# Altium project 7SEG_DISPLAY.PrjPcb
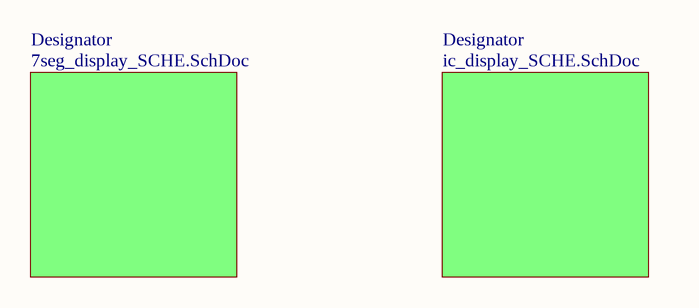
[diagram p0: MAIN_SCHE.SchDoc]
3 sheets, 658 parts. Net scope: global (net labels, ports and power ports of the same name join across sheets).
Board file: 7SEG_PCB.PcbDoc
Sheets:
  MAIN_SCHE.SchDoc
    Designator = 7seg_display_SCHE.SchDoc
    Designator = ic_display_SCHE.SchDoc

## Sheet MAIN_SCHE.SchDoc
size A; SheetNumber: 1; SheetTotal: 3

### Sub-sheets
Designator = 7seg_display_SCHE.SchDoc: no entries
Designator = ic_display_SCHE.SchDoc: no entries

## Sheet 7seg_display_SCHE.SchDoc
size C; SheetNumber: 3; SheetTotal: 3
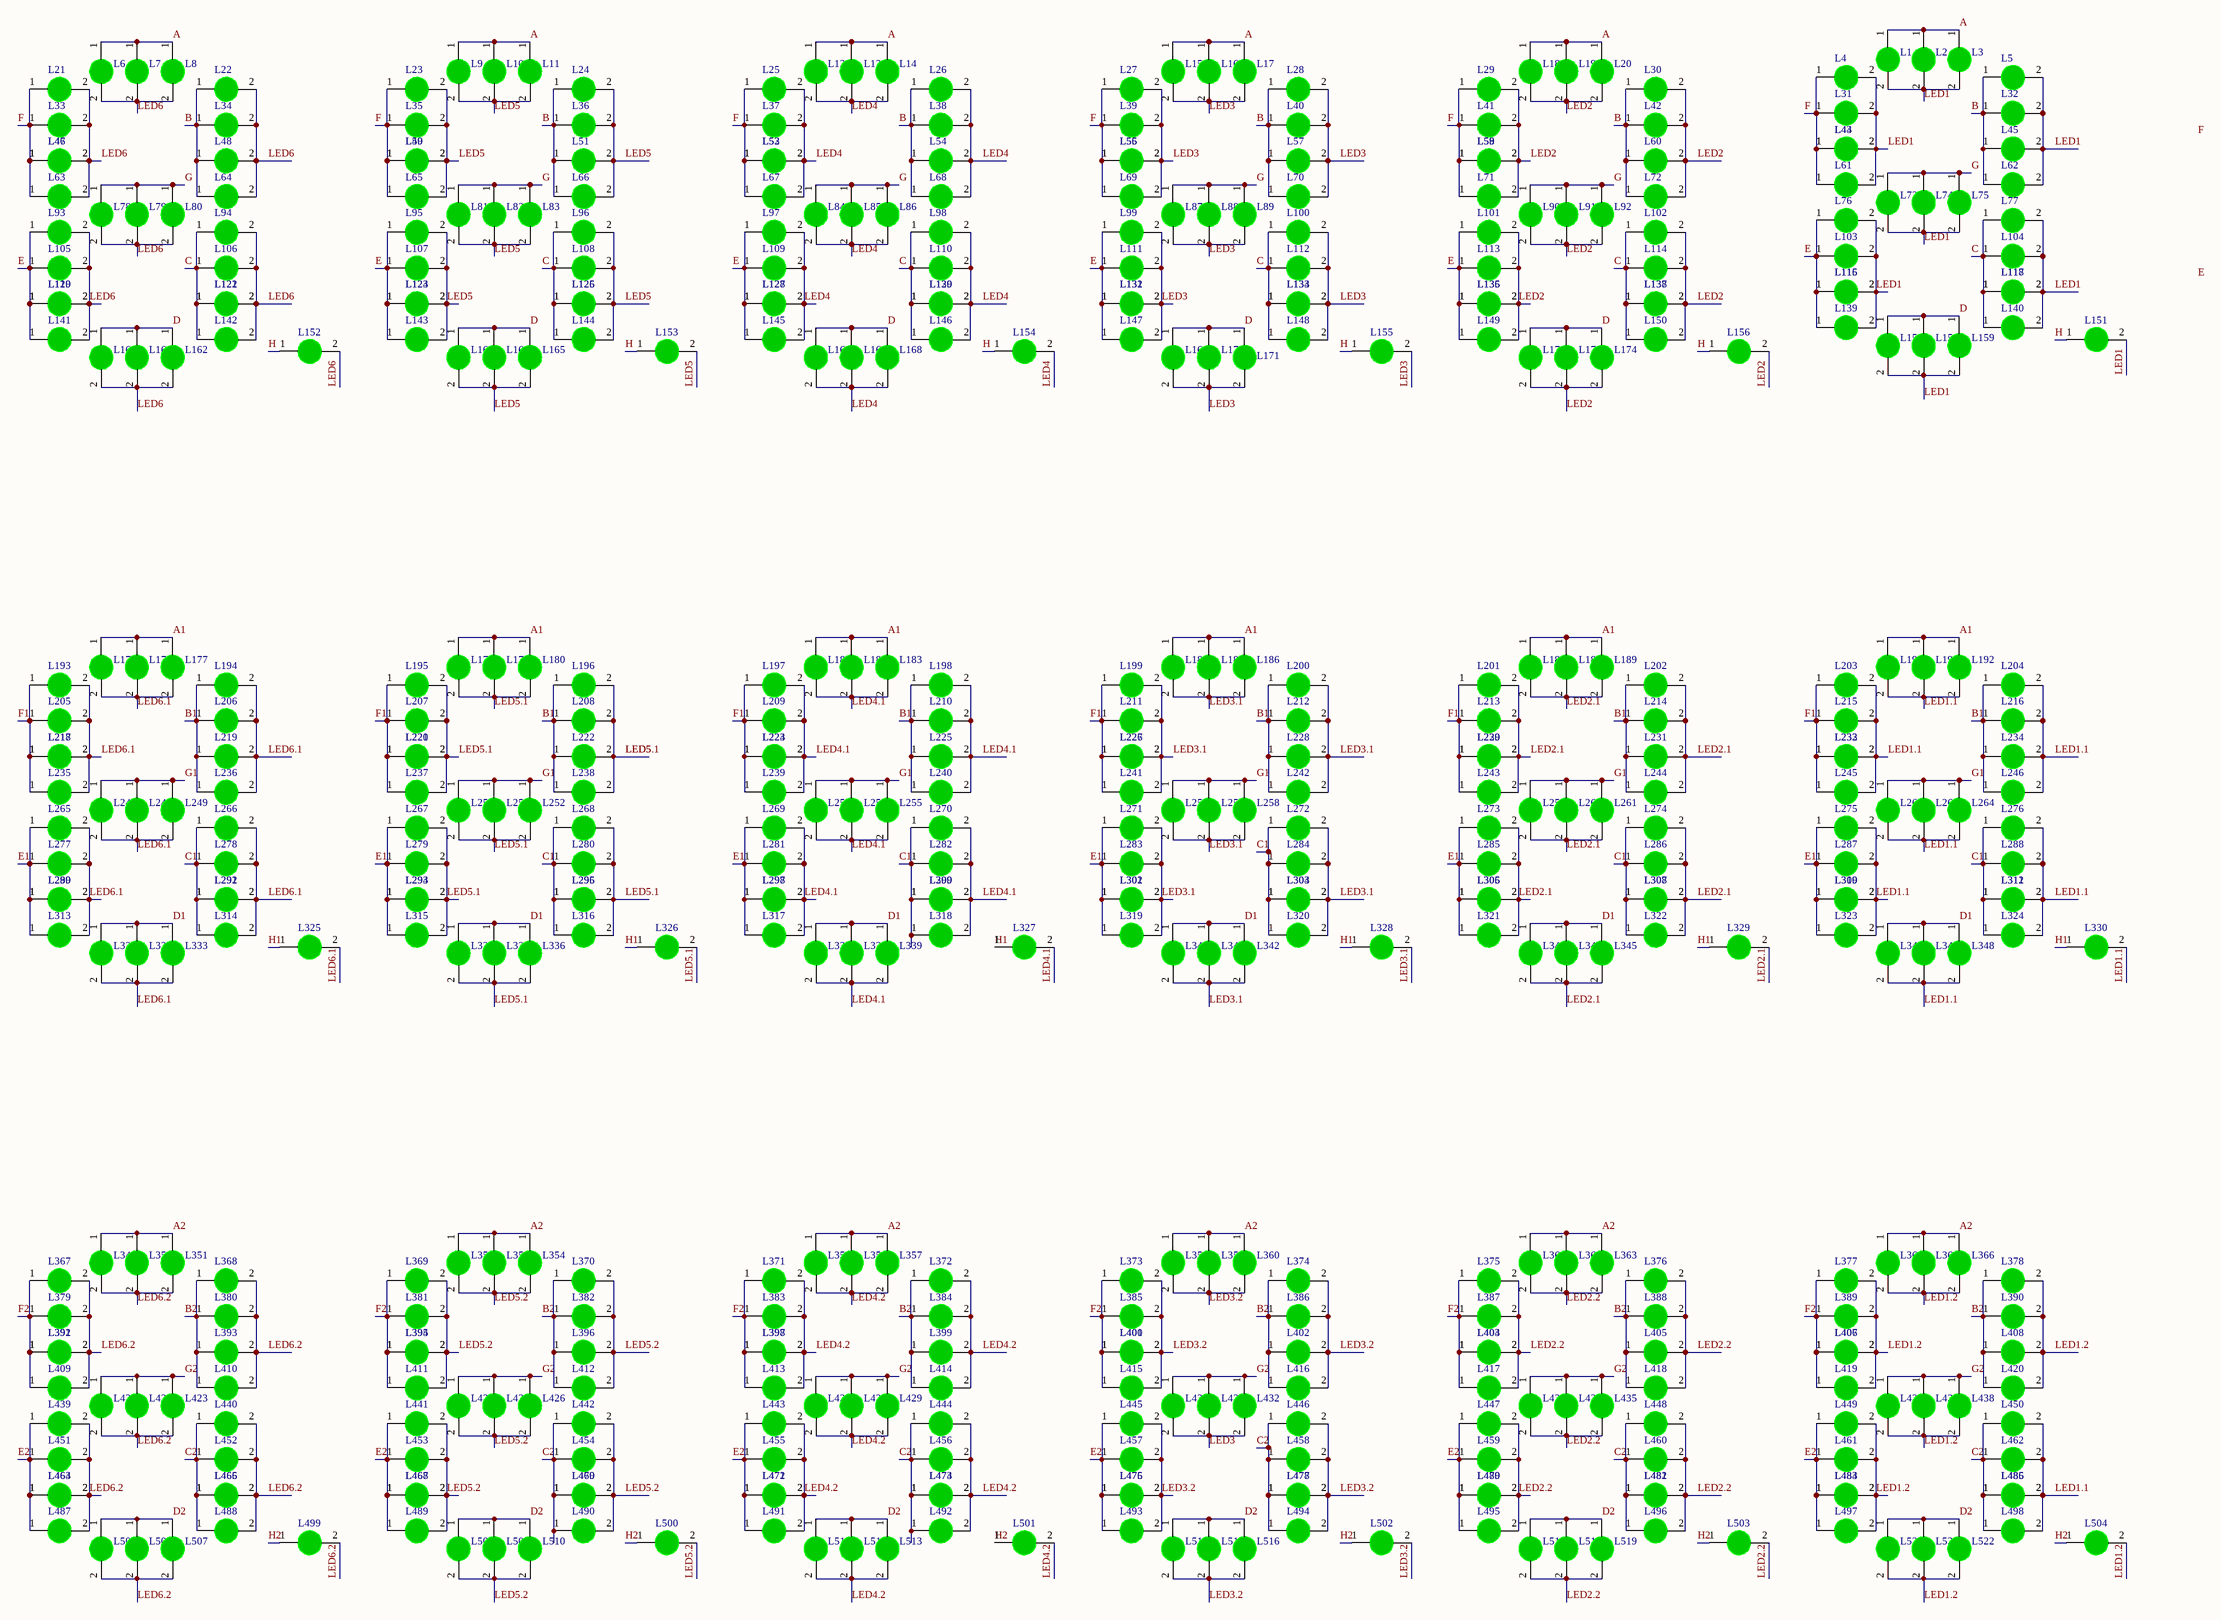
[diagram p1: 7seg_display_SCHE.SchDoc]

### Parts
L1  LED 3528  [LED-3528-GREEN]  (value not drawn)
L2  LED 3528  [LED-3528-GREEN]  (value not drawn)
L3  LED 3528  [LED-3528-GREEN]  (value not drawn)
L4  LED 3528  [LED-3528-GREEN]  (value not drawn)
L5  LED 3528  [LED-3528-GREEN]  (value not drawn)
L6  LED 3528  [LED-3528-GREEN]  (value not drawn)
L7  LED 3528  [LED-3528-GREEN]  (value not drawn)
L8  LED 3528  [LED-3528-GREEN]  (value not drawn)
L9  LED 3528  [LED-3528-GREEN]  (value not drawn)
L10  LED 3528  [LED-3528-GREEN]  (value not drawn)
L11  LED 3528  [LED-3528-GREEN]  (value not drawn)
L12  LED 3528  [LED-3528-GREEN]  (value not drawn)
L13  LED 3528  [LED-3528-GREEN]  (value not drawn)
L14  LED 3528  [LED-3528-GREEN]  (value not drawn)
L15  LED 3528  [LED-3528-GREEN]  (value not drawn)
L16  LED 3528  [LED-3528-GREEN]  (value not drawn)
L17  LED 3528  [LED-3528-GREEN]  (value not drawn)
L18  LED 3528  [LED-3528-GREEN]  (value not drawn)
L19  LED 3528  [LED-3528-GREEN]  (value not drawn)
L20  LED 3528  [LED-3528-GREEN]  (value not drawn)
L21  LED 3528  [LED-3528-GREEN]  (value not drawn)
L22  LED 3528  [LED-3528-GREEN]  (value not drawn)
L23  LED 3528  [LED-3528-GREEN]  (value not drawn)
L24  LED 3528  [LED-3528-GREEN]  (value not drawn)
L25  LED 3528  [LED-3528-GREEN]  (value not drawn)
L26  LED 3528  [LED-3528-GREEN]  (value not drawn)
L27  LED 3528  [LED-3528-GREEN]  (value not drawn)
L28  LED 3528  [LED-3528-GREEN]  (value not drawn)
L29  LED 3528  [LED-3528-GREEN]  (value not drawn)
L30  LED 3528  [LED-3528-GREEN]  (value not drawn)
L31  LED 3528  [LED-3528-GREEN]  (value not drawn)
L32  LED 3528  [LED-3528-GREEN]  (value not drawn)
L33  LED 3528  [LED-3528-GREEN]  (value not drawn)
L34  LED 3528  [LED-3528-GREEN]  (value not drawn)
L35  LED 3528  [LED-3528-GREEN]  (value not drawn)
L36  LED 3528  [LED-3528-GREEN]  (value not drawn)
L37  LED 3528  [LED-3528-GREEN]  (value not drawn)
L38  LED 3528  [LED-3528-GREEN]  (value not drawn)
L39  LED 3528  [LED-3528-GREEN]  (value not drawn)
L40  LED 3528  [LED-3528-GREEN]  (value not drawn)
L41  LED 3528  [LED-3528-GREEN]  (value not drawn)
L42  LED 3528  [LED-3528-GREEN]  (value not drawn)
L43  LED 3528  [LED-3528-GREEN]  (value not drawn)
L44  LED 3528  [LED-3528-GREEN]  (value not drawn)
L45  LED 3528  [LED-3528-GREEN]  (value not drawn)
L46  LED 3528  [LED-3528-GREEN]  (value not drawn)
L47  LED 3528  [LED-3528-GREEN]  (value not drawn)
L48  LED 3528  [LED-3528-GREEN]  (value not drawn)
L49  LED 3528  [LED-3528-GREEN]  (value not drawn)
L50  LED 3528  [LED-3528-GREEN]  (value not drawn)
L51  LED 3528  [LED-3528-GREEN]  (value not drawn)
L52  LED 3528  [LED-3528-GREEN]  (value not drawn)
L53  LED 3528  [LED-3528-GREEN]  (value not drawn)
L54  LED 3528  [LED-3528-GREEN]  (value not drawn)
L55  LED 3528  [LED-3528-GREEN]  (value not drawn)
L56  LED 3528  [LED-3528-GREEN]  (value not drawn)
L57  LED 3528  [LED-3528-GREEN]  (value not drawn)
L58  LED 3528  [LED-3528-GREEN]  (value not drawn)
L59  LED 3528  [LED-3528-GREEN]  (value not drawn)
L60  LED 3528  [LED-3528-GREEN]  (value not drawn)
L61  LED 3528  [LED-3528-GREEN]  (value not drawn)
L62  LED 3528  [LED-3528-GREEN]  (value not drawn)
L63  LED 3528  [LED-3528-GREEN]  (value not drawn)
L64  LED 3528  [LED-3528-GREEN]  (value not drawn)
L65  LED 3528  [LED-3528-GREEN]  (value not drawn)
L66  LED 3528  [LED-3528-GREEN]  (value not drawn)
L67  LED 3528  [LED-3528-GREEN]  (value not drawn)
L68  LED 3528  [LED-3528-GREEN]  (value not drawn)
L69  LED 3528  [LED-3528-GREEN]  (value not drawn)
L70  LED 3528  [LED-3528-GREEN]  (value not drawn)
L71  LED 3528  [LED-3528-GREEN]  (value not drawn)
L72  LED 3528  [LED-3528-GREEN]  (value not drawn)
L73  LED 3528  [LED-3528-GREEN]  (value not drawn)
L74  LED 3528  [LED-3528-GREEN]  (value not drawn)
L75  LED 3528  [LED-3528-GREEN]  (value not drawn)
L76  LED 3528  [LED-3528-GREEN]  (value not drawn)
L77  LED 3528  [LED-3528-GREEN]  (value not drawn)
L78  LED 3528  [LED-3528-GREEN]  (value not drawn)
L79  LED 3528  [LED-3528-GREEN]  (value not drawn)
L80  LED 3528  [LED-3528-GREEN]  (value not drawn)
L81  LED 3528  [LED-3528-GREEN]  (value not drawn)
L82  LED 3528  [LED-3528-GREEN]  (value not drawn)
L83  LED 3528  [LED-3528-GREEN]  (value not drawn)
L84  LED 3528  [LED-3528-GREEN]  (value not drawn)
L85  LED 3528  [LED-3528-GREEN]  (value not drawn)
L86  LED 3528  [LED-3528-GREEN]  (value not drawn)
L87  LED 3528  [LED-3528-GREEN]  (value not drawn)
L88  LED 3528  [LED-3528-GREEN]  (value not drawn)
L89  LED 3528  [LED-3528-GREEN]  (value not drawn)
L90  LED 3528  [LED-3528-GREEN]  (value not drawn)
L91  LED 3528  [LED-3528-GREEN]  (value not drawn)
L92  LED 3528  [LED-3528-GREEN]  (value not drawn)
L93  LED 3528  [LED-3528-GREEN]  (value not drawn)
L94  LED 3528  [LED-3528-GREEN]  (value not drawn)
L95  LED 3528  [LED-3528-GREEN]  (value not drawn)
L96  LED 3528  [LED-3528-GREEN]  (value not drawn)
L97  LED 3528  [LED-3528-GREEN]  (value not drawn)
L98  LED 3528  [LED-3528-GREEN]  (value not drawn)
L99  LED 3528  [LED-3528-GREEN]  (value not drawn)
L100  LED 3528  [LED-3528-GREEN]  (value not drawn)
L101  LED 3528  [LED-3528-GREEN]  (value not drawn)
L102  LED 3528  [LED-3528-GREEN]  (value not drawn)
L103  LED 3528  [LED-3528-GREEN]  (value not drawn)
L104  LED 3528  [LED-3528-GREEN]  (value not drawn)
L105  LED 3528  [LED-3528-GREEN]  (value not drawn)
L106  LED 3528  [LED-3528-GREEN]  (value not drawn)
L107  LED 3528  [LED-3528-GREEN]  (value not drawn)
L108  LED 3528  [LED-3528-GREEN]  (value not drawn)
L109  LED 3528  [LED-3528-GREEN]  (value not drawn)
L110  LED 3528  [LED-3528-GREEN]  (value not drawn)
L111  LED 3528  [LED-3528-GREEN]  (value not drawn)
L112  LED 3528  [LED-3528-GREEN]  (value not drawn)
L113  LED 3528  [LED-3528-GREEN]  (value not drawn)
L114  LED 3528  [LED-3528-GREEN]  (value not drawn)
L115  LED 3528  [LED-3528-GREEN]  (value not drawn)
L116  LED 3528  [LED-3528-GREEN]  (value not drawn)
L117  LED 3528  [LED-3528-GREEN]  (value not drawn)
L118  LED 3528  [LED-3528-GREEN]  (value not drawn)
L119  LED 3528  [LED-3528-GREEN]  (value not drawn)
L120  LED 3528  [LED-3528-GREEN]  (value not drawn)
L121  LED 3528  [LED-3528-GREEN]  (value not drawn)
L122  LED 3528  [LED-3528-GREEN]  (value not drawn)
L123  LED 3528  [LED-3528-GREEN]  (value not drawn)
L124  LED 3528  [LED-3528-GREEN]  (value not drawn)
L125  LED 3528  [LED-3528-GREEN]  (value not drawn)
L126  LED 3528  [LED-3528-GREEN]  (value not drawn)
L127  LED 3528  [LED-3528-GREEN]  (value not drawn)
L128  LED 3528  [LED-3528-GREEN]  (value not drawn)
L129  LED 3528  [LED-3528-GREEN]  (value not drawn)
L130  LED 3528  [LED-3528-GREEN]  (value not drawn)
L131  LED 3528  [LED-3528-GREEN]  (value not drawn)
L132  LED 3528  [LED-3528-GREEN]  (value not drawn)
L133  LED 3528  [LED-3528-GREEN]  (value not drawn)
L134  LED 3528  [LED-3528-GREEN]  (value not drawn)
L135  LED 3528  [LED-3528-GREEN]  (value not drawn)
L136  LED 3528  [LED-3528-GREEN]  (value not drawn)
L137  LED 3528  [LED-3528-GREEN]  (value not drawn)
L138  LED 3528  [LED-3528-GREEN]  (value not drawn)
L139  LED 3528  [LED-3528-GREEN]  (value not drawn)
L140  LED 3528  [LED-3528-GREEN]  (value not drawn)
L141  LED 3528  [LED-3528-GREEN]  (value not drawn)
L142  LED 3528  [LED-3528-GREEN]  (value not drawn)
L143  LED 3528  [LED-3528-GREEN]  (value not drawn)
L144  LED 3528  [LED-3528-GREEN]  (value not drawn)
L145  LED 3528  [LED-3528-GREEN]  (value not drawn)
L146  LED 3528  [LED-3528-GREEN]  (value not drawn)
L147  LED 3528  [LED-3528-GREEN]  (value not drawn)
L148  LED 3528  [LED-3528-GREEN]  (value not drawn)
L149  LED 3528  [LED-3528-GREEN]  (value not drawn)
L150  LED 3528  [LED-3528-GREEN]  (value not drawn)
L151  LED 3528  [LED-3528-GREEN]  (value not drawn)
L152  LED 3528  [LED-3528-GREEN]  (value not drawn)
L153  LED 3528  [LED-3528-GREEN]  (value not drawn)
L154  LED 3528  [LED-3528-GREEN]  (value not drawn)
L155  LED 3528  [LED-3528-GREEN]  (value not drawn)
L156  LED 3528  [LED-3528-GREEN]  (value not drawn)
L157  LED 3528  [LED-3528-GREEN]  (value not drawn)
L158  LED 3528  [LED-3528-GREEN]  (value not drawn)
L159  LED 3528  [LED-3528-GREEN]  (value not drawn)
L160  LED 3528  [LED-3528-GREEN]  (value not drawn)
L161  LED 3528  [LED-3528-GREEN]  (value not drawn)
L162  LED 3528  [LED-3528-GREEN]  (value not drawn)
L163  LED 3528  [LED-3528-GREEN]  (value not drawn)
L164  LED 3528  [LED-3528-GREEN]  (value not drawn)
L165  LED 3528  [LED-3528-GREEN]  (value not drawn)
L166  LED 3528  [LED-3528-GREEN]  (value not drawn)
L167  LED 3528  [LED-3528-GREEN]  (value not drawn)
L168  LED 3528  [LED-3528-GREEN]  (value not drawn)
L169  LED 3528  [LED-3528-GREEN]  (value not drawn)
L170  LED 3528  [LED-3528-GREEN]  (value not drawn)
L171  LED 3528  [LED-3528-GREEN]  (value not drawn)
L172  LED 3528  [LED-3528-GREEN]  (value not drawn)
L173  LED 3528  [LED-3528-GREEN]  (value not drawn)
L174  LED 3528  [LED-3528-GREEN]  (value not drawn)
L175  LED 3528  [LED-3528-GREEN]  (value not drawn)
L176  LED 3528  [LED-3528-GREEN]  (value not drawn)
L177  LED 3528  [LED-3528-GREEN]  (value not drawn)
L178  LED 3528  [LED-3528-GREEN]  (value not drawn)
L179  LED 3528  [LED-3528-GREEN]  (value not drawn)
L180  LED 3528  [LED-3528-GREEN]  (value not drawn)
L181  LED 3528  [LED-3528-GREEN]  (value not drawn)
L182  LED 3528  [LED-3528-GREEN]  (value not drawn)
L183  LED 3528  [LED-3528-GREEN]  (value not drawn)
L184  LED 3528  [LED-3528-GREEN]  (value not drawn)
L185  LED 3528  [LED-3528-GREEN]  (value not drawn)
L186  LED 3528  [LED-3528-GREEN]  (value not drawn)
L187  LED 3528  [LED-3528-GREEN]  (value not drawn)
L188  LED 3528  [LED-3528-GREEN]  (value not drawn)
L189  LED 3528  [LED-3528-GREEN]  (value not drawn)
L190  LED 3528  [LED-3528-GREEN]  (value not drawn)
L191  LED 3528  [LED-3528-GREEN]  (value not drawn)
L192  LED 3528  [LED-3528-GREEN]  (value not drawn)
L193  LED 3528  [LED-3528-GREEN]  (value not drawn)
L194  LED 3528  [LED-3528-GREEN]  (value not drawn)
L195  LED 3528  [LED-3528-GREEN]  (value not drawn)
L196  LED 3528  [LED-3528-GREEN]  (value not drawn)
L197  LED 3528  [LED-3528-GREEN]  (value not drawn)
L198  LED 3528  [LED-3528-GREEN]  (value not drawn)
L199  LED 3528  [LED-3528-GREEN]  (value not drawn)
L200  LED 3528  [LED-3528-GREEN]  (value not drawn)
L201  LED 3528  [LED-3528-GREEN]  (value not drawn)
L202  LED 3528  [LED-3528-GREEN]  (value not drawn)
L203  LED 3528  [LED-3528-GREEN]  (value not drawn)
L204  LED 3528  [LED-3528-GREEN]  (value not drawn)
L205  LED 3528  [LED-3528-GREEN]  (value not drawn)
L206  LED 3528  [LED-3528-GREEN]  (value not drawn)
L207  LED 3528  [LED-3528-GREEN]  (value not drawn)
L208  LED 3528  [LED-3528-GREEN]  (value not drawn)
L209  LED 3528  [LED-3528-GREEN]  (value not drawn)
L210  LED 3528  [LED-3528-GREEN]  (value not drawn)
L211  LED 3528  [LED-3528-GREEN]  (value not drawn)
L212  LED 3528  [LED-3528-GREEN]  (value not drawn)
L213  LED 3528  [LED-3528-GREEN]  (value not drawn)
L214  LED 3528  [LED-3528-GREEN]  (value not drawn)
L215  LED 3528  [LED-3528-GREEN]  (value not drawn)
L216  LED 3528  [LED-3528-GREEN]  (value not drawn)
L217  LED 3528  [LED-3528-GREEN]  (value not drawn)
L218  LED 3528  [LED-3528-GREEN]  (value not drawn)
L219  LED 3528  [LED-3528-GREEN]  (value not drawn)
L220  LED 3528  [LED-3528-GREEN]  (value not drawn)
L221  LED 3528  [LED-3528-GREEN]  (value not drawn)
L222  LED 3528  [LED-3528-GREEN]  (value not drawn)
L223  LED 3528  [LED-3528-GREEN]  (value not drawn)
L224  LED 3528  [LED-3528-GREEN]  (value not drawn)
L225  LED 3528  [LED-3528-GREEN]  (value not drawn)
L226  LED 3528  [LED-3528-GREEN]  (value not drawn)
L227  LED 3528  [LED-3528-GREEN]  (value not drawn)
L228  LED 3528  [LED-3528-GREEN]  (value not drawn)
L229  LED 3528  [LED-3528-GREEN]  (value not drawn)
L230  LED 3528  [LED-3528-GREEN]  (value not drawn)
L231  LED 3528  [LED-3528-GREEN]  (value not drawn)
L232  LED 3528  [LED-3528-GREEN]  (value not drawn)
L233  LED 3528  [LED-3528-GREEN]  (value not drawn)
L234  LED 3528  [LED-3528-GREEN]  (value not drawn)
L235  LED 3528  [LED-3528-GREEN]  (value not drawn)
L236  LED 3528  [LED-3528-GREEN]  (value not drawn)
L237  LED 3528  [LED-3528-GREEN]  (value not drawn)
L238  LED 3528  [LED-3528-GREEN]  (value not drawn)
L239  LED 3528  [LED-3528-GREEN]  (value not drawn)
L240  LED 3528  [LED-3528-GREEN]  (value not drawn)
L241  LED 3528  [LED-3528-GREEN]  (value not drawn)
L242  LED 3528  [LED-3528-GREEN]  (value not drawn)
L243  LED 3528  [LED-3528-GREEN]  (value not drawn)
L244  LED 3528  [LED-3528-GREEN]  (value not drawn)
L245  LED 3528  [LED-3528-GREEN]  (value not drawn)
L246  LED 3528  [LED-3528-GREEN]  (value not drawn)
L247  LED 3528  [LED-3528-GREEN]  (value not drawn)
L248  LED 3528  [LED-3528-GREEN]  (value not drawn)
L249  LED 3528  [LED-3528-GREEN]  (value not drawn)
L250  LED 3528  [LED-3528-GREEN]  (value not drawn)
L251  LED 3528  [LED-3528-GREEN]  (value not drawn)
L252  LED 3528  [LED-3528-GREEN]  (value not drawn)
L253  LED 3528  [LED-3528-GREEN]  (value not drawn)
L254  LED 3528  [LED-3528-GREEN]  (value not drawn)
L255  LED 3528  [LED-3528-GREEN]  (value not drawn)
L256  LED 3528  [LED-3528-GREEN]  (value not drawn)
L257  LED 3528  [LED-3528-GREEN]  (value not drawn)
L258  LED 3528  [LED-3528-GREEN]  (value not drawn)
L259  LED 3528  [LED-3528-GREEN]  (value not drawn)
L260  LED 3528  [LED-3528-GREEN]  (value not drawn)
L261  LED 3528  [LED-3528-GREEN]  (value not drawn)
L262  LED 3528  [LED-3528-GREEN]  (value not drawn)
L263  LED 3528  [LED-3528-GREEN]  (value not drawn)
L264  LED 3528  [LED-3528-GREEN]  (value not drawn)
L265  LED 3528  [LED-3528-GREEN]  (value not drawn)
L266  LED 3528  [LED-3528-GREEN]  (value not drawn)
L267  LED 3528  [LED-3528-GREEN]  (value not drawn)
L268  LED 3528  [LED-3528-GREEN]  (value not drawn)
L269  LED 3528  [LED-3528-GREEN]  (value not drawn)
L270  LED 3528  [LED-3528-GREEN]  (value not drawn)
L271  LED 3528  [LED-3528-GREEN]  (value not drawn)
L272  LED 3528  [LED-3528-GREEN]  (value not drawn)
L273  LED 3528  [LED-3528-GREEN]  (value not drawn)
L274  LED 3528  [LED-3528-GREEN]  (value not drawn)
L275  LED 3528  [LED-3528-GREEN]  (value not drawn)
L276  LED 3528  [LED-3528-GREEN]  (value not drawn)
L277  LED 3528  [LED-3528-GREEN]  (value not drawn)
L278  LED 3528  [LED-3528-GREEN]  (value not drawn)
L279  LED 3528  [LED-3528-GREEN]  (value not drawn)
L280  LED 3528  [LED-3528-GREEN]  (value not drawn)
L281  LED 3528  [LED-3528-GREEN]  (value not drawn)
L282  LED 3528  [LED-3528-GREEN]  (value not drawn)
L283  LED 3528  [LED-3528-GREEN]  (value not drawn)
L284  LED 3528  [LED-3528-GREEN]  (value not drawn)
L285  LED 3528  [LED-3528-GREEN]  (value not drawn)
L286  LED 3528  [LED-3528-GREEN]  (value not drawn)
L287  LED 3528  [LED-3528-GREEN]  (value not drawn)
L288  LED 3528  [LED-3528-GREEN]  (value not drawn)
L289  LED 3528  [LED-3528-GREEN]  (value not drawn)
L290  LED 3528  [LED-3528-GREEN]  (value not drawn)
L291  LED 3528  [LED-3528-GREEN]  (value not drawn)
L292  LED 3528  [LED-3528-GREEN]  (value not drawn)
L293  LED 3528  [LED-3528-GREEN]  (value not drawn)
L294  LED 3528  [LED-3528-GREEN]  (value not drawn)
L295  LED 3528  [LED-3528-GREEN]  (value not drawn)
L296  LED 3528  [LED-3528-GREEN]  (value not drawn)
L297  LED 3528  [LED-3528-GREEN]  (value not drawn)
L298  LED 3528  [LED-3528-GREEN]  (value not drawn)
L299  LED 3528  [LED-3528-GREEN]  (value not drawn)
L300  LED 3528  [LED-3528-GREEN]  (value not drawn)
L301  LED 3528  [LED-3528-GREEN]  (value not drawn)
L302  LED 3528  [LED-3528-GREEN]  (value not drawn)
L303  LED 3528  [LED-3528-GREEN]  (value not drawn)
L304  LED 3528  [LED-3528-GREEN]  (value not drawn)
L305  LED 3528  [LED-3528-GREEN]  (value not drawn)
L306  LED 3528  [LED-3528-GREEN]  (value not drawn)
L307  LED 3528  [LED-3528-GREEN]  (value not drawn)
L308  LED 3528  [LED-3528-GREEN]  (value not drawn)
L309  LED 3528  [LED-3528-GREEN]  (value not drawn)
L310  LED 3528  [LED-3528-GREEN]  (value not drawn)
L311  LED 3528  [LED-3528-GREEN]  (value not drawn)
L312  LED 3528  [LED-3528-GREEN]  (value not drawn)
L313  LED 3528  [LED-3528-GREEN]  (value not drawn)
L314  LED 3528  [LED-3528-GREEN]  (value not drawn)
L315  LED 3528  [LED-3528-GREEN]  (value not drawn)
L316  LED 3528  [LED-3528-GREEN]  (value not drawn)
L317  LED 3528  [LED-3528-GREEN]  (value not drawn)
L318  LED 3528  [LED-3528-GREEN]  (value not drawn)
L319  LED 3528  [LED-3528-GREEN]  (value not drawn)
L320  LED 3528  [LED-3528-GREEN]  (value not drawn)
L321  LED 3528  [LED-3528-GREEN]  (value not drawn)
L322  LED 3528  [LED-3528-GREEN]  (value not drawn)
L323  LED 3528  [LED-3528-GREEN]  (value not drawn)
L324  LED 3528  [LED-3528-GREEN]  (value not drawn)
L325  LED 3528  [LED-3528-GREEN]  (value not drawn)
L326  LED 3528  [LED-3528-GREEN]  (value not drawn)
L327  LED 3528  [LED-3528-GREEN]  (value not drawn)
L328  LED 3528  [LED-3528-GREEN]  (value not drawn)
L329  LED 3528  [LED-3528-GREEN]  (value not drawn)
L330  LED 3528  [LED-3528-GREEN]  (value not drawn)
L331  LED 3528  [LED-3528-GREEN]  (value not drawn)
L332  LED 3528  [LED-3528-GREEN]  (value not drawn)
L333  LED 3528  [LED-3528-GREEN]  (value not drawn)
L334  LED 3528  [LED-3528-GREEN]  (value not drawn)
L335  LED 3528  [LED-3528-GREEN]  (value not drawn)
L336  LED 3528  [LED-3528-GREEN]  (value not drawn)
L337  LED 3528  [LED-3528-GREEN]  (value not drawn)
L338  LED 3528  [LED-3528-GREEN]  (value not drawn)
L339  LED 3528  [LED-3528-GREEN]  (value not drawn)
L340  LED 3528  [LED-3528-GREEN]  (value not drawn)
L341  LED 3528  [LED-3528-GREEN]  (value not drawn)
L342  LED 3528  [LED-3528-GREEN]  (value not drawn)
L343  LED 3528  [LED-3528-GREEN]  (value not drawn)
L344  LED 3528  [LED-3528-GREEN]  (value not drawn)
L345  LED 3528  [LED-3528-GREEN]  (value not drawn)
L346  LED 3528  [LED-3528-GREEN]  (value not drawn)
L347  LED 3528  [LED-3528-GREEN]  (value not drawn)
L348  LED 3528  [LED-3528-GREEN]  (value not drawn)
L349  LED 3528  [LED-3528-GREEN]  (value not drawn)
L350  LED 3528  [LED-3528-GREEN]  (value not drawn)
L351  LED 3528  [LED-3528-GREEN]  (value not drawn)
L352  LED 3528  [LED-3528-GREEN]  (value not drawn)
L353  LED 3528  [LED-3528-GREEN]  (value not drawn)
L354  LED 3528  [LED-3528-GREEN]  (value not drawn)
L355  LED 3528  [LED-3528-GREEN]  (value not drawn)
L356  LED 3528  [LED-3528-GREEN]  (value not drawn)
L357  LED 3528  [LED-3528-GREEN]  (value not drawn)
L358  LED 3528  [LED-3528-GREEN]  (value not drawn)
L359  LED 3528  [LED-3528-GREEN]  (value not drawn)
L360  LED 3528  [LED-3528-GREEN]  (value not drawn)
L361  LED 3528  [LED-3528-GREEN]  (value not drawn)
L362  LED 3528  [LED-3528-GREEN]  (value not drawn)
L363  LED 3528  [LED-3528-GREEN]  (value not drawn)
L364  LED 3528  [LED-3528-GREEN]  (value not drawn)
L365  LED 3528  [LED-3528-GREEN]  (value not drawn)
L366  LED 3528  [LED-3528-GREEN]  (value not drawn)
L367  LED 3528  [LED-3528-GREEN]  (value not drawn)
L368  LED 3528  [LED-3528-GREEN]  (value not drawn)
L369  LED 3528  [LED-3528-GREEN]  (value not drawn)
L370  LED 3528  [LED-3528-GREEN]  (value not drawn)
L371  LED 3528  [LED-3528-GREEN]  (value not drawn)
L372  LED 3528  [LED-3528-GREEN]  (value not drawn)
L373  LED 3528  [LED-3528-GREEN]  (value not drawn)
L374  LED 3528  [LED-3528-GREEN]  (value not drawn)
L375  LED 3528  [LED-3528-GREEN]  (value not drawn)
L376  LED 3528  [LED-3528-GREEN]  (value not drawn)
L377  LED 3528  [LED-3528-GREEN]  (value not drawn)
L378  LED 3528  [LED-3528-GREEN]  (value not drawn)
L379  LED 3528  [LED-3528-GREEN]  (value not drawn)
L380  LED 3528  [LED-3528-GREEN]  (value not drawn)
L381  LED 3528  [LED-3528-GREEN]  (value not drawn)
L382  LED 3528  [LED-3528-GREEN]  (value not drawn)
L383  LED 3528  [LED-3528-GREEN]  (value not drawn)
L384  LED 3528  [LED-3528-GREEN]  (value not drawn)
L385  LED 3528  [LED-3528-GREEN]  (value not drawn)
L386  LED 3528  [LED-3528-GREEN]  (value not drawn)
L387  LED 3528  [LED-3528-GREEN]  (value not drawn)
L388  LED 3528  [LED-3528-GREEN]  (value not drawn)
L389  LED 3528  [LED-3528-GREEN]  (value not drawn)
L390  LED 3528  [LED-3528-GREEN]  (value not drawn)
L391  LED 3528  [LED-3528-GREEN]  (value not drawn)
L392  LED 3528  [LED-3528-GREEN]  (value not drawn)
L393  LED 3528  [LED-3528-GREEN]  (value not drawn)
L394  LED 3528  [LED-3528-GREEN]  (value not drawn)
L395  LED 3528  [LED-3528-GREEN]  (value not drawn)
L396  LED 3528  [LED-3528-GREEN]  (value not drawn)
L397  LED 3528  [LED-3528-GREEN]  (value not drawn)
L398  LED 3528  [LED-3528-GREEN]  (value not drawn)
L399  LED 3528  [LED-3528-GREEN]  (value not drawn)
L400  LED 3528  [LED-3528-GREEN]  (value not drawn)
L401  LED 3528  [LED-3528-GREEN]  (value not drawn)
L402  LED 3528  [LED-3528-GREEN]  (value not drawn)
L403  LED 3528  [LED-3528-GREEN]  (value not drawn)
L404  LED 3528  [LED-3528-GREEN]  (value not drawn)
L405  LED 3528  [LED-3528-GREEN]  (value not drawn)
L406  LED 3528  [LED-3528-GREEN]  (value not drawn)
L407  LED 3528  [LED-3528-GREEN]  (value not drawn)
L408  LED 3528  [LED-3528-GREEN]  (value not drawn)
L409  LED 3528  [LED-3528-GREEN]  (value not drawn)
L410  LED 3528  [LED-3528-GREEN]  (value not drawn)
L411  LED 3528  [LED-3528-GREEN]  (value not drawn)
L412  LED 3528  [LED-3528-GREEN]  (value not drawn)
L413  LED 3528  [LED-3528-GREEN]  (value not drawn)
L414  LED 3528  [LED-3528-GREEN]  (value not drawn)
L415  LED 3528  [LED-3528-GREEN]  (value not drawn)
L416  LED 3528  [LED-3528-GREEN]  (value not drawn)
L417  LED 3528  [LED-3528-GREEN]  (value not drawn)
L418  LED 3528  [LED-3528-GREEN]  (value not drawn)
L419  LED 3528  [LED-3528-GREEN]  (value not drawn)
L420  LED 3528  [LED-3528-GREEN]  (value not drawn)
L421  LED 3528  [LED-3528-GREEN]  (value not drawn)
L422  LED 3528  [LED-3528-GREEN]  (value not drawn)
L423  LED 3528  [LED-3528-GREEN]  (value not drawn)
L424  LED 3528  [LED-3528-GREEN]  (value not drawn)
L425  LED 3528  [LED-3528-GREEN]  (value not drawn)
L426  LED 3528  [LED-3528-GREEN]  (value not drawn)
L427  LED 3528  [LED-3528-GREEN]  (value not drawn)
L428  LED 3528  [LED-3528-GREEN]  (value not drawn)
L429  LED 3528  [LED-3528-GREEN]  (value not drawn)
L430  LED 3528  [LED-3528-GREEN]  (value not drawn)
L431  LED 3528  [LED-3528-GREEN]  (value not drawn)
L432  LED 3528  [LED-3528-GREEN]  (value not drawn)
L433  LED 3528  [LED-3528-GREEN]  (value not drawn)
L434  LED 3528  [LED-3528-GREEN]  (value not drawn)
L435  LED 3528  [LED-3528-GREEN]  (value not drawn)
L436  LED 3528  [LED-3528-GREEN]  (value not drawn)
L437  LED 3528  [LED-3528-GREEN]  (value not drawn)
L438  LED 3528  [LED-3528-GREEN]  (value not drawn)
L439  LED 3528  [LED-3528-GREEN]  (value not drawn)
L440  LED 3528  [LED-3528-GREEN]  (value not drawn)
L441  LED 3528  [LED-3528-GREEN]  (value not drawn)
L442  LED 3528  [LED-3528-GREEN]  (value not drawn)
L443  LED 3528  [LED-3528-GREEN]  (value not drawn)
L444  LED 3528  [LED-3528-GREEN]  (value not drawn)
L445  LED 3528  [LED-3528-GREEN]  (value not drawn)
L446  LED 3528  [LED-3528-GREEN]  (value not drawn)
L447  LED 3528  [LED-3528-GREEN]  (value not drawn)
L448  LED 3528  [LED-3528-GREEN]  (value not drawn)
L449  LED 3528  [LED-3528-GREEN]  (value not drawn)
L450  LED 3528  [LED-3528-GREEN]  (value not drawn)
L451  LED 3528  [LED-3528-GREEN]  (value not drawn)
L452  LED 3528  [LED-3528-GREEN]  (value not drawn)
L453  LED 3528  [LED-3528-GREEN]  (value not drawn)
L454  LED 3528  [LED-3528-GREEN]  (value not drawn)
L455  LED 3528  [LED-3528-GREEN]  (value not drawn)
L456  LED 3528  [LED-3528-GREEN]  (value not drawn)
L457  LED 3528  [LED-3528-GREEN]  (value not drawn)
L458  LED 3528  [LED-3528-GREEN]  (value not drawn)
L459  LED 3528  [LED-3528-GREEN]  (value not drawn)
L460  LED 3528  [LED-3528-GREEN]  (value not drawn)
L461  LED 3528  [LED-3528-GREEN]  (value not drawn)
L462  LED 3528  [LED-3528-GREEN]  (value not drawn)
L463  LED 3528  [LED-3528-GREEN]  (value not drawn)
L464  LED 3528  [LED-3528-GREEN]  (value not drawn)
L465  LED 3528  [LED-3528-GREEN]  (value not drawn)
L466  LED 3528  [LED-3528-GREEN]  (value not drawn)
L467  LED 3528  [LED-3528-GREEN]  (value not drawn)
L468  LED 3528  [LED-3528-GREEN]  (value not drawn)
L469  LED 3528  [LED-3528-GREEN]  (value not drawn)
L470  LED 3528  [LED-3528-GREEN]  (value not drawn)
L471  LED 3528  [LED-3528-GREEN]  (value not drawn)
L472  LED 3528  [LED-3528-GREEN]  (value not drawn)
L473  LED 3528  [LED-3528-GREEN]  (value not drawn)
L474  LED 3528  [LED-3528-GREEN]  (value not drawn)
L475  LED 3528  [LED-3528-GREEN]  (value not drawn)
L476  LED 3528  [LED-3528-GREEN]  (value not drawn)
L477  LED 3528  [LED-3528-GREEN]  (value not drawn)
L478  LED 3528  [LED-3528-GREEN]  (value not drawn)
L479  LED 3528  [LED-3528-GREEN]  (value not drawn)
L480  LED 3528  [LED-3528-GREEN]  (value not drawn)
L481  LED 3528  [LED-3528-GREEN]  (value not drawn)
L482  LED 3528  [LED-3528-GREEN]  (value not drawn)
L483  LED 3528  [LED-3528-GREEN]  (value not drawn)
L484  LED 3528  [LED-3528-GREEN]  (value not drawn)
L485  LED 3528  [LED-3528-GREEN]  (value not drawn)
L486  LED 3528  [LED-3528-GREEN]  (value not drawn)
L487  LED 3528  [LED-3528-GREEN]  (value not drawn)
L488  LED 3528  [LED-3528-GREEN]  (value not drawn)
L489  LED 3528  [LED-3528-GREEN]  (value not drawn)
L490  LED 3528  [LED-3528-GREEN]  (value not drawn)
L491  LED 3528  [LED-3528-GREEN]  (value not drawn)
L492  LED 3528  [LED-3528-GREEN]  (value not drawn)
L493  LED 3528  [LED-3528-GREEN]  (value not drawn)
L494  LED 3528  [LED-3528-GREEN]  (value not drawn)
L495  LED 3528  [LED-3528-GREEN]  (value not drawn)
L496  LED 3528  [LED-3528-GREEN]  (value not drawn)
L497  LED 3528  [LED-3528-GREEN]  (value not drawn)
L498  LED 3528  [LED-3528-GREEN]  (value not drawn)
L499  LED 3528  [LED-3528-GREEN]  (value not drawn)
L500  LED 3528  [LED-3528-GREEN]  (value not drawn)
L501  LED 3528  [LED-3528-GREEN]  (value not drawn)
L502  LED 3528  [LED-3528-GREEN]  (value not drawn)
L503  LED 3528  [LED-3528-GREEN]  (value not drawn)
L504  LED 3528  [LED-3528-GREEN]  (value not drawn)
L505  LED 3528  [LED-3528-GREEN]  (value not drawn)
L506  LED 3528  [LED-3528-GREEN]  (value not drawn)
L507  LED 3528  [LED-3528-GREEN]  (value not drawn)
L508  LED 3528  [LED-3528-GREEN]  (value not drawn)
L509  LED 3528  [LED-3528-GREEN]  (value not drawn)
L510  LED 3528  [LED-3528-GREEN]  (value not drawn)
L511  LED 3528  [LED-3528-GREEN]  (value not drawn)
L512  LED 3528  [LED-3528-GREEN]  (value not drawn)
L513  LED 3528  [LED-3528-GREEN]  (value not drawn)
L514  LED 3528  [LED-3528-GREEN]  (value not drawn)
L515  LED 3528  [LED-3528-GREEN]  (value not drawn)
L516  LED 3528  [LED-3528-GREEN]  (value not drawn)
L517  LED 3528  [LED-3528-GREEN]  (value not drawn)
L518  LED 3528  [LED-3528-GREEN]  (value not drawn)
L519  LED 3528  [LED-3528-GREEN]  (value not drawn)
L520  LED 3528  [LED-3528-GREEN]  (value not drawn)
L521  LED 3528  [LED-3528-GREEN]  (value not drawn)
L522  LED 3528  [LED-3528-GREEN]  (value not drawn)

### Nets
A: L1.1(A) L2.1(A) L3.1(A) L6.1(A) L7.1(A) L8.1(A) L9.1(A) L10.1(A) L11.1(A) L12.1(A) L13.1(A) L14.1(A) L15.1(A) L16.1(A) L17.1(A) L18.1(A) L19.1(A) L20.1(A)
A1: L175.1(A) L176.1(A) L177.1(A) L178.1(A) L179.1(A) L180.1(A) L181.1(A) L182.1(A) L183.1(A) L184.1(A) L185.1(A) L186.1(A) L187.1(A) L188.1(A) L189.1(A) L190.1(A) L191.1(A) L192.1(A)
A2: L349.1(A) L350.1(A) L351.1(A) L352.1(A) L353.1(A) L354.1(A) L355.1(A) L356.1(A) L357.1(A) L358.1(A) L359.1(A) L360.1(A) L361.1(A) L362.1(A) L363.1(A) L364.1(A) L365.1(A) L366.1(A)
B: L5.1(A) L22.1(A) L24.1(A) L26.1(A) L28.1(A) L30.1(A) L32.1(A) L34.1(A) L36.1(A) L38.1(A) L40.1(A) L42.1(A) L45.1(A) L48.1(A) L51.1(A) L54.1(A) L57.1(A) L60.1(A) L62.1(A) L64.1(A) L66.1(A) L68.1(A) L70.1(A) L72.1(A)
B1: L194.1(A) L196.1(A) L198.1(A) L200.1(A) L202.1(A) L204.1(A) L206.1(A) L208.1(A) L210.1(A) L212.1(A) L214.1(A) L216.1(A) L219.1(A) L222.1(A) L225.1(A) L228.1(A) L231.1(A) L234.1(A) L236.1(A) L238.1(A) L240.1(A) L242.1(A) L244.1(A) L246.1(A)
B2: L368.1(A) L370.1(A) L372.1(A) L374.1(A) L376.1(A) L378.1(A) L380.1(A) L382.1(A) L384.1(A) L386.1(A) L388.1(A) L390.1(A) L393.1(A) L396.1(A) L399.1(A) L402.1(A) L405.1(A) L408.1(A) L410.1(A) L412.1(A) L414.1(A) L416.1(A) L418.1(A) L420.1(A)
C: L77.1(A) L94.1(A) L96.1(A) L98.1(A) L100.1(A) L102.1(A) L104.1(A) L106.1(A) L108.1(A) L110.1(A) L112.1(A) L114.1(A) L117.1(A) L118.1(A) L121.1(A) L122.1(A) L125.1(A) L126.1(A) L129.1(A) L130.1(A) L133.1(A) L134.1(A) L137.1(A) L138.1(A) L140.1(A) L142.1(A) L144.1(A) L146.1(A) L148.1(A) L150.1(A)
C1: L266.1(A) L268.1(A) L270.1(A) L272.1(A) L274.1(A) L276.1(A) L278.1(A) L280.1(A) L282.1(A) L284.1(A) L286.1(A) L288.1(A) L291.1(A) L292.1(A) L295.1(A) L296.1(A) L299.1(A) L300.1(A) L303.1(A) L304.1(A) L307.1(A) L308.1(A) L311.1(A) L312.1(A) L314.1(A) L316.1(A) L318.1(A) L320.1(A) L322.1(A) L324.1(A)
C2: L440.1(A) L442.1(A) L444.1(A) L446.1(A) L448.1(A) L450.1(A) L452.1(A) L454.1(A) L456.1(A) L458.1(A) L460.1(A) L462.1(A) L465.1(A) L466.1(A) L469.1(A) L470.1(A) L473.1(A) L474.1(A) L477.1(A) L478.1(A) L481.1(A) L482.1(A) L485.1(A) L486.1(A) L488.1(A) L490.1(A) L492.1(A) L494.1(A) L496.1(A) L498.1(A)
D: L157.1(A) L158.1(A) L159.1(A) L160.1(A) L161.1(A) L162.1(A) L163.1(A) L164.1(A) L165.1(A) L166.1(A) L167.1(A) L168.1(A) L169.1(A) L170.1(A) L171.1(A) L172.1(A) L173.1(A) L174.1(A)
D1: L331.1(A) L332.1(A) L333.1(A) L334.1(A) L335.1(A) L336.1(A) L337.1(A) L338.1(A) L339.1(A) L340.1(A) L341.1(A) L342.1(A) L343.1(A) L344.1(A) L345.1(A) L346.1(A) L347.1(A) L348.1(A)
D2: L505.1(A) L506.1(A) L507.1(A) L508.1(A) L509.1(A) L510.1(A) L511.1(A) L512.1(A) L513.1(A) L514.1(A) L515.1(A) L516.1(A) L517.1(A) L518.1(A) L519.1(A) L520.1(A) L521.1(A) L522.1(A)
E: L76.1(A) L93.1(A) L95.1(A) L97.1(A) L99.1(A) L101.1(A) L103.1(A) L105.1(A) L107.1(A) L109.1(A) L111.1(A) L113.1(A) L115.1(A) L116.1(A) L119.1(A) L120.1(A) L123.1(A) L124.1(A) L127.1(A) L128.1(A) L131.1(A) L132.1(A) L135.1(A) L136.1(A) L139.1(A) L141.1(A) L143.1(A) L145.1(A) L147.1(A) L149.1(A)
E1: L265.1(A) L267.1(A) L269.1(A) L271.1(A) L273.1(A) L275.1(A) L277.1(A) L279.1(A) L281.1(A) L283.1(A) L285.1(A) L287.1(A) L289.1(A) L290.1(A) L293.1(A) L294.1(A) L297.1(A) L298.1(A) L301.1(A) L302.1(A) L305.1(A) L306.1(A) L309.1(A) L310.1(A) L313.1(A) L315.1(A) L317.1(A) L319.1(A) L321.1(A) L323.1(A)
E2: L439.1(A) L441.1(A) L443.1(A) L445.1(A) L447.1(A) L449.1(A) L451.1(A) L453.1(A) L455.1(A) L457.1(A) L459.1(A) L461.1(A) L463.1(A) L464.1(A) L467.1(A) L468.1(A) L471.1(A) L472.1(A) L475.1(A) L476.1(A) L479.1(A) L480.1(A) L483.1(A) L484.1(A) L487.1(A) L489.1(A) L491.1(A) L493.1(A) L495.1(A) L497.1(A)
F: L4.1(A) L21.1(A) L23.1(A) L25.1(A) L27.1(A) L29.1(A) L31.1(A) L33.1(A) L35.1(A) L37.1(A) L39.1(A) L41.1(A) L43.1(A) L44.1(A) L46.1(A) L47.1(A) L49.1(A) L50.1(A) L52.1(A) L53.1(A) L55.1(A) L56.1(A) L58.1(A) L59.1(A) L61.1(A) L63.1(A) L65.1(A) L67.1(A) L69.1(A) L71.1(A)
F1: L193.1(A) L195.1(A) L197.1(A) L199.1(A) L201.1(A) L203.1(A) L205.1(A) L207.1(A) L209.1(A) L211.1(A) L213.1(A) L215.1(A) L217.1(A) L218.1(A) L220.1(A) L221.1(A) L223.1(A) L224.1(A) L226.1(A) L227.1(A) L229.1(A) L230.1(A) L232.1(A) L233.1(A) L235.1(A) L237.1(A) L239.1(A) L241.1(A) L243.1(A) L245.1(A)
F2: L367.1(A) L369.1(A) L371.1(A) L373.1(A) L375.1(A) L377.1(A) L379.1(A) L381.1(A) L383.1(A) L385.1(A) L387.1(A) L389.1(A) L391.1(A) L392.1(A) L394.1(A) L395.1(A) L397.1(A) L398.1(A) L400.1(A) L401.1(A) L403.1(A) L404.1(A) L406.1(A) L407.1(A) L409.1(A) L411.1(A) L413.1(A) L415.1(A) L417.1(A) L419.1(A)
G: L73.1(A) L74.1(A) L75.1(A) L78.1(A) L79.1(A) L80.1(A) L81.1(A) L82.1(A) L83.1(A) L84.1(A) L85.1(A) L86.1(A) L87.1(A) L88.1(A) L89.1(A) L90.1(A) L91.1(A) L92.1(A)
G1: L247.1(A) L248.1(A) L249.1(A) L250.1(A) L251.1(A) L252.1(A) L253.1(A) L254.1(A) L255.1(A) L256.1(A) L257.1(A) L258.1(A) L259.1(A) L260.1(A) L261.1(A) L262.1(A) L263.1(A) L264.1(A)
G2: L421.1(A) L422.1(A) L423.1(A) L424.1(A) L425.1(A) L426.1(A) L427.1(A) L428.1(A) L429.1(A) L430.1(A) L431.1(A) L432.1(A) L433.1(A) L434.1(A) L435.1(A) L436.1(A) L437.1(A) L438.1(A)
H: L151.1(A) L152.1(A) L153.1(A) L154.1(A) L155.1(A) L156.1(A)
H1: L325.1(A) L326.1(A) L327.1(A) L328.1(A) L329.1(A) L330.1(A)
H2: L499.1(A) L500.1(A) L501.1(A) L502.1(A) L503.1(A) L504.1(A)
LED1: L1.2(K) L2.2(K) L3.2(K) L4.2(K) L5.2(K) L31.2(K) L32.2(K) L43.2(K) L44.2(K) L45.2(K) L61.2(K) L62.2(K) L73.2(K) L74.2(K) L75.2(K) L76.2(K) L77.2(K) L103.2(K) L104.2(K) L115.2(K) L116.2(K) L117.2(K) L118.2(K) L139.2(K) L140.2(K) L151.2(K) L157.2(K) L158.2(K) L159.2(K)
LED1.1: L190.2(K) L191.2(K) L192.2(K) L203.2(K) L204.2(K) L215.2(K) L216.2(K) L232.2(K) L233.2(K) L234.2(K) L245.2(K) L246.2(K) L262.2(K) L263.2(K) L264.2(K) L275.2(K) L276.2(K) L287.2(K) L288.2(K) L309.2(K) L310.2(K) L311.2(K) L312.2(K) L323.2(K) L324.2(K) L330.2(K) L346.2(K) L347.2(K) L348.2(K) L450.2(K) L462.2(K) L485.2(K) L486.2(K) L498.2(K)
LED1.2: L364.2(K) L365.2(K) L366.2(K) L377.2(K) L378.2(K) L389.2(K) L390.2(K) L406.2(K) L407.2(K) L408.2(K) L419.2(K) L420.2(K) L436.2(K) L437.2(K) L438.2(K) L449.2(K) L461.2(K) L483.2(K) L484.2(K) L497.2(K) L504.2(K) L520.2(K) L521.2(K) L522.2(K)
LED2: L18.2(K) L19.2(K) L20.2(K) L29.2(K) L30.2(K) L41.2(K) L42.2(K) L58.2(K) L59.2(K) L60.2(K) L71.2(K) L72.2(K) L90.2(K) L91.2(K) L92.2(K) L101.2(K) L102.2(K) L113.2(K) L114.2(K) L135.2(K) L136.2(K) L137.2(K) L138.2(K) L149.2(K) L150.2(K) L156.2(K) L172.2(K) L173.2(K) L174.2(K)
LED2.1: L187.2(K) L188.2(K) L189.2(K) L201.2(K) L202.2(K) L213.2(K) L214.2(K) L229.2(K) L230.2(K) L231.2(K) L243.2(K) L244.2(K) L259.2(K) L260.2(K) L261.2(K) L273.2(K) L274.2(K) L285.2(K) L286.2(K) L305.2(K) L306.2(K) L307.2(K) L308.2(K) L321.2(K) L322.2(K) L329.2(K) L343.2(K) L344.2(K) L345.2(K)
LED2.2: L361.2(K) L362.2(K) L363.2(K) L375.2(K) L376.2(K) L387.2(K) L388.2(K) L403.2(K) L404.2(K) L405.2(K) L417.2(K) L418.2(K) L433.2(K) L434.2(K) L435.2(K) L447.2(K) L448.2(K) L459.2(K) L460.2(K) L479.2(K) L480.2(K) L481.2(K) L482.2(K) L495.2(K) L496.2(K) L503.2(K) L517.2(K) L518.2(K) L519.2(K)
LED3: L15.2(K) L16.2(K) L17.2(K) L27.2(K) L28.2(K) L39.2(K) L40.2(K) L55.2(K) L56.2(K) L57.2(K) L69.2(K) L70.2(K) L87.2(K) L88.2(K) L89.2(K) L99.2(K) L100.2(K) L111.2(K) L112.2(K) L131.2(K) L132.2(K) L133.2(K) L134.2(K) L147.2(K) L148.2(K) L155.2(K) L169.2(K) L170.2(K) L171.2(K) L430.2(K) L431.2(K) L432.2(K)
LED3.1: L184.2(K) L185.2(K) L186.2(K) L199.2(K) L200.2(K) L211.2(K) L212.2(K) L226.2(K) L227.2(K) L228.2(K) L241.2(K) L242.2(K) L256.2(K) L257.2(K) L258.2(K) L271.2(K) L272.2(K) L283.2(K) L284.2(K) L301.2(K) L302.2(K) L303.2(K) L304.2(K) L319.2(K) L320.2(K) L328.2(K) L340.2(K) L341.2(K) L342.2(K)
LED3.2: L358.2(K) L359.2(K) L360.2(K) L373.2(K) L374.2(K) L385.2(K) L386.2(K) L400.2(K) L401.2(K) L402.2(K) L415.2(K) L416.2(K) L445.2(K) L446.2(K) L457.2(K) L458.2(K) L475.2(K) L476.2(K) L477.2(K) L478.2(K) L493.2(K) L494.2(K) L502.2(K) L514.2(K) L515.2(K) L516.2(K)
LED4: L12.2(K) L13.2(K) L14.2(K) L25.2(K) L26.2(K) L37.2(K) L38.2(K) L52.2(K) L53.2(K) L54.2(K) L67.2(K) L68.2(K) L84.2(K) L85.2(K) L86.2(K) L97.2(K) L98.2(K) L109.2(K) L110.2(K) L127.2(K) L128.2(K) L129.2(K) L130.2(K) L145.2(K) L146.2(K) L154.2(K) L166.2(K) L167.2(K) L168.2(K)
LED4.1: L181.2(K) L182.2(K) L183.2(K) L197.2(K) L198.2(K) L209.2(K) L210.2(K) L223.2(K) L224.2(K) L225.2(K) L239.2(K) L240.2(K) L253.2(K) L254.2(K) L255.2(K) L269.2(K) L270.2(K) L281.2(K) L282.2(K) L297.2(K) L298.2(K) L299.2(K) L300.2(K) L317.2(K) L318.2(K) L327.2(K) L337.2(K) L338.2(K) L339.2(K)
LED4.2: L355.2(K) L356.2(K) L357.2(K) L371.2(K) L372.2(K) L383.2(K) L384.2(K) L397.2(K) L398.2(K) L399.2(K) L413.2(K) L414.2(K) L427.2(K) L428.2(K) L429.2(K) L443.2(K) L444.2(K) L455.2(K) L456.2(K) L471.2(K) L472.2(K) L473.2(K) L474.2(K) L491.2(K) L492.2(K) L501.2(K) L511.2(K) L512.2(K) L513.2(K)
LED5: L9.2(K) L10.2(K) L11.2(K) L23.2(K) L24.2(K) L35.2(K) L36.2(K) L49.2(K) L50.2(K) L51.2(K) L65.2(K) L66.2(K) L81.2(K) L82.2(K) L83.2(K) L95.2(K) L96.2(K) L107.2(K) L108.2(K) L123.2(K) L124.2(K) L125.2(K) L126.2(K) L143.2(K) L144.2(K) L153.2(K) L163.2(K) L164.2(K) L165.2(K) L178.2(K) L179.2(K) L180.2(K) L195.2(K) L196.2(K) L207.2(K) L208.2(K) L220.2(K) L221.2(K) L222.2(K) L237.2(K) L238.2(K) L250.2(K) L251.2(K) L252.2(K) L267.2(K) L268.2(K) L279.2(K) L280.2(K) L293.2(K) L294.2(K) L295.2(K) L296.2(K) L315.2(K) L316.2(K) L326.2(K) L334.2(K) L335.2(K) L336.2(K)  [also labelled LED5.1]
LED5.2: L352.2(K) L353.2(K) L354.2(K) L369.2(K) L370.2(K) L381.2(K) L382.2(K) L394.2(K) L395.2(K) L396.2(K) L411.2(K) L412.2(K) L424.2(K) L425.2(K) L426.2(K) L441.2(K) L442.2(K) L453.2(K) L454.2(K) L467.2(K) L468.2(K) L469.2(K) L470.2(K) L489.2(K) L490.2(K) L500.2(K) L508.2(K) L509.2(K) L510.2(K)
LED6: L6.2(K) L7.2(K) L8.2(K) L21.2(K) L22.2(K) L33.2(K) L34.2(K) L46.2(K) L47.2(K) L48.2(K) L63.2(K) L64.2(K) L78.2(K) L79.2(K) L80.2(K) L93.2(K) L94.2(K) L105.2(K) L106.2(K) L119.2(K) L120.2(K) L121.2(K) L122.2(K) L141.2(K) L142.2(K) L152.2(K) L160.2(K) L161.2(K) L162.2(K)
LED6.1: L175.2(K) L176.2(K) L177.2(K) L193.2(K) L194.2(K) L205.2(K) L206.2(K) L217.2(K) L218.2(K) L219.2(K) L235.2(K) L236.2(K) L247.2(K) L248.2(K) L249.2(K) L265.2(K) L266.2(K) L277.2(K) L278.2(K) L289.2(K) L290.2(K) L291.2(K) L292.2(K) L313.2(K) L314.2(K) L325.2(K) L331.2(K) L332.2(K) L333.2(K)
LED6.2: L349.2(K) L350.2(K) L351.2(K) L367.2(K) L368.2(K) L379.2(K) L380.2(K) L391.2(K) L392.2(K) L393.2(K) L409.2(K) L410.2(K) L421.2(K) L422.2(K) L423.2(K) L439.2(K) L440.2(K) L451.2(K) L452.2(K) L463.2(K) L464.2(K) L465.2(K) L466.2(K) L487.2(K) L488.2(K) L499.2(K) L505.2(K) L506.2(K) L507.2(K)

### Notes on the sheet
- Labels drawn without touching a wire or pin: E, F

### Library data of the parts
L1-L522 = LED 3528 Xanh La: Dán; Don_Vi: Con; Ma_Hang: MH005547; Ten_Linh_Kien: LED3528 Màu Xanh Lá

## Sheet ic_display_SCHE.SchDoc
size B; SheetNumber: 2; SheetTotal: 3
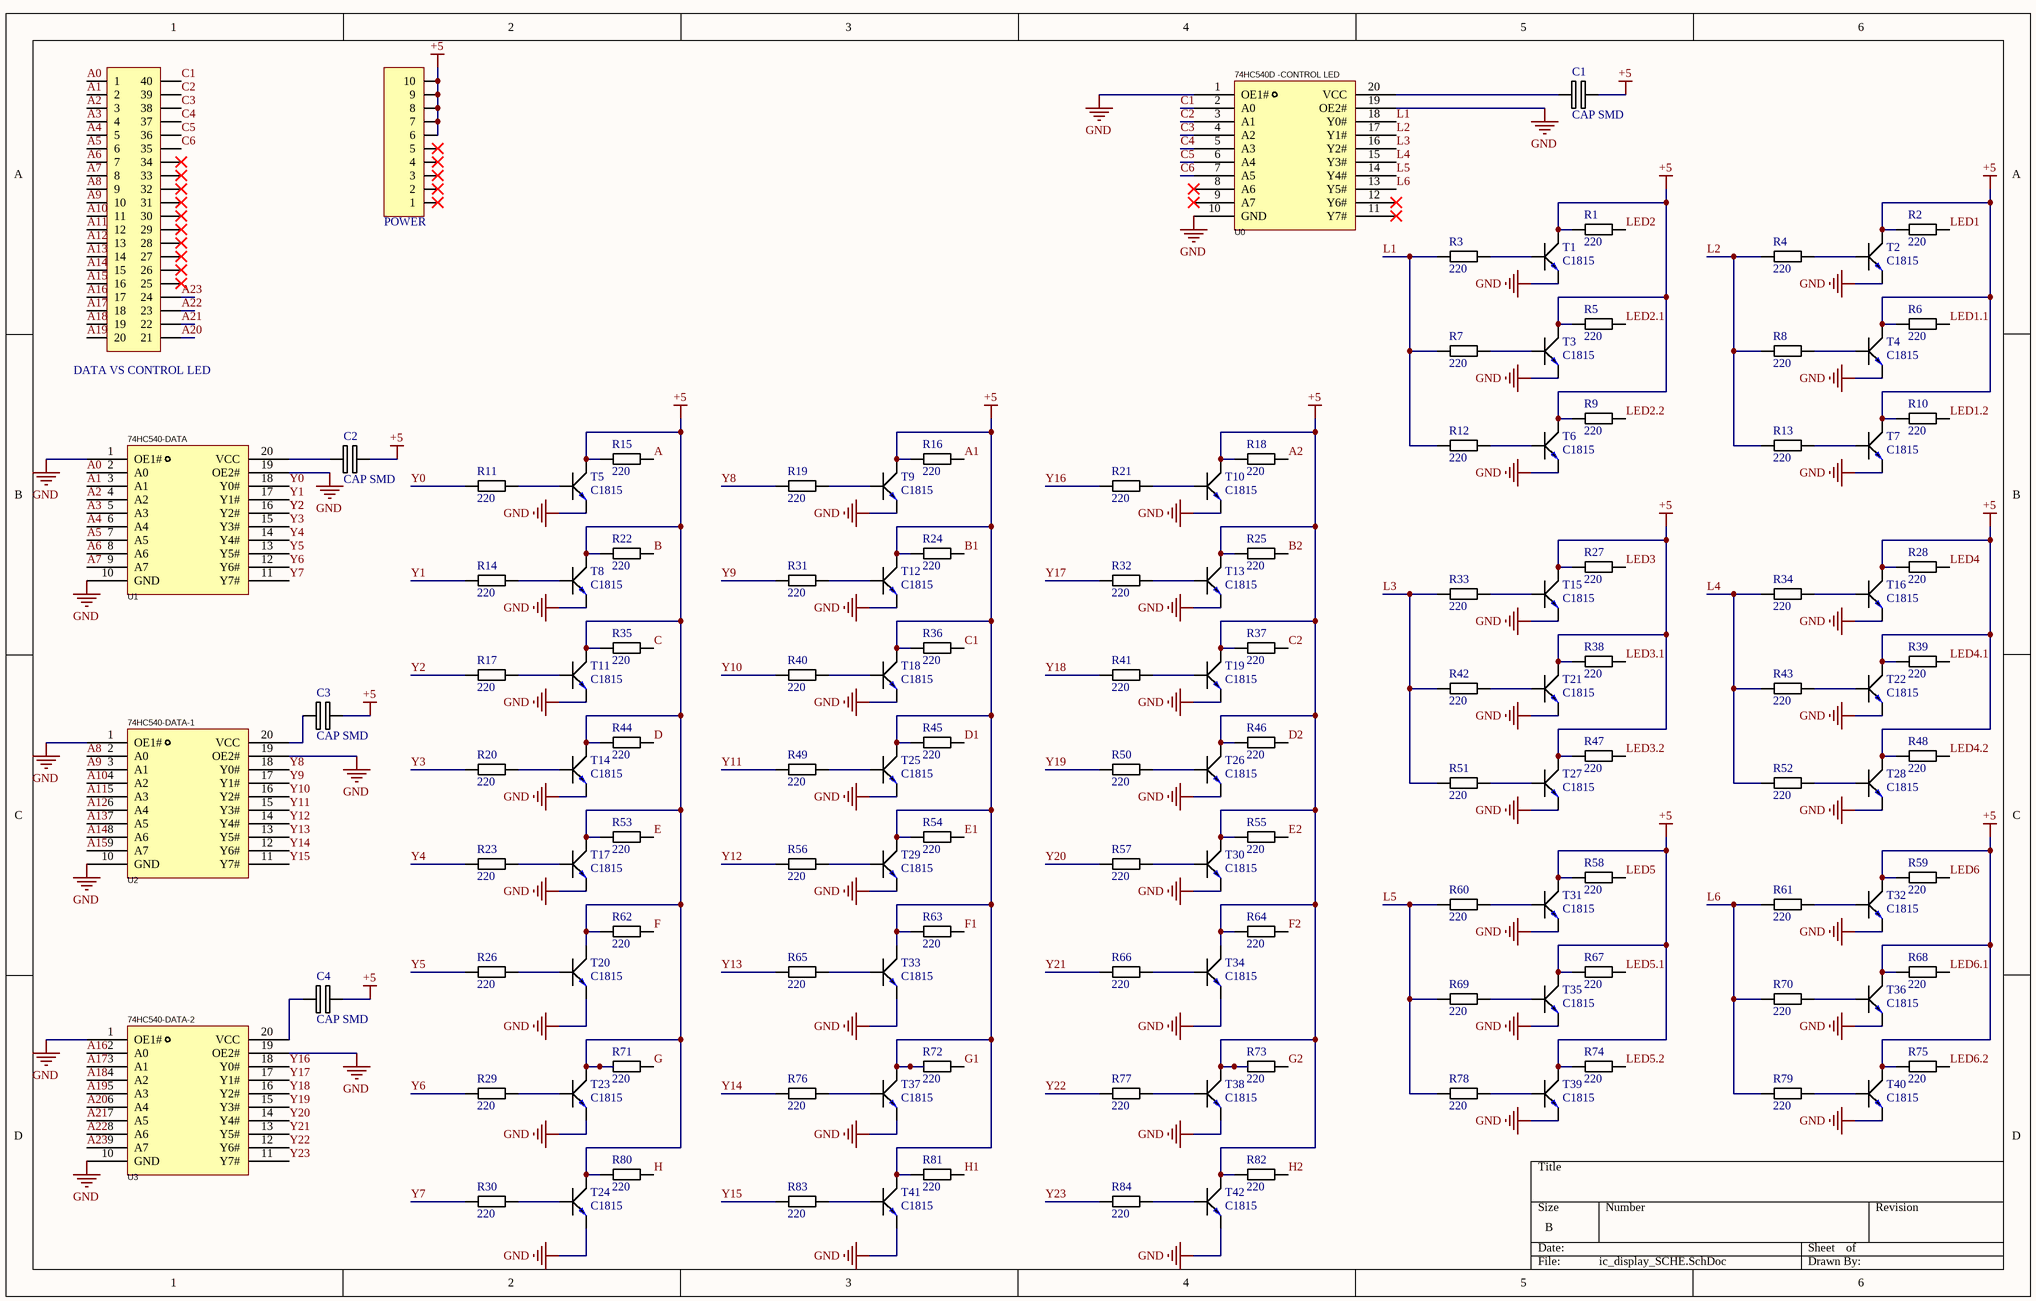
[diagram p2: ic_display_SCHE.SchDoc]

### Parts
C1  CAP SMD  [C-0805]
C2  CAP SMD  [C-0805]
C3  CAP SMD  [C-0805]
C4  CAP SMD  [C-0805]
JP1  DATA VS CONTROL LED  [JP 2x20 DT]
JP?  POWER  [JP 1x10 DT]
R1  220  [Resistor 0805]
R2  220  [Resistor 0805]
R3  220  [Resistor 0805]
R4  220  [Resistor 0805]
R5  220  [Resistor 0805]
R6  220  [Resistor 0805]
R7  220  [Resistor 0805]
R8  220  [Resistor 0805]
R9  220  [Resistor 0805]
R10  220  [Resistor 0805]
R11  220  [Resistor 0805]
R12  220  [Resistor 0805]
R13  220  [Resistor 0805]
R14  220  [Resistor 0805]
R15  220  [Resistor 0805]
R16  220  [Resistor 0805]
R17  220  [Resistor 0805]
R18  220  [Resistor 0805]
R19  220  [Resistor 0805]
R20  220  [Resistor 0805]
R21  220  [Resistor 0805]
R22  220  [Resistor 0805]
R23  220  [Resistor 0805]
R24  220  [Resistor 0805]
R25  220  [Resistor 0805]
R26  220  [Resistor 0805]
R27  220  [Resistor 0805]
R28  220  [Resistor 0805]
R29  220  [Resistor 0805]
R30  220  [Resistor 0805]
R31  220  [Resistor 0805]
R32  220  [Resistor 0805]
R33  220  [Resistor 0805]
R34  220  [Resistor 0805]
R35  220  [Resistor 0805]
R36  220  [Resistor 0805]
R37  220  [Resistor 0805]
R38  220  [Resistor 0805]
R39  220  [Resistor 0805]
R40  220  [Resistor 0805]
R41  220  [Resistor 0805]
R42  220  [Resistor 0805]
R43  220  [Resistor 0805]
R44  220  [Resistor 0805]
R45  220  [Resistor 0805]
R46  220  [Resistor 0805]
R47  220  [Resistor 0805]
R48  220  [Resistor 0805]
R49  220  [Resistor 0805]
R50  220  [Resistor 0805]
R51  220  [Resistor 0805]
R52  220  [Resistor 0805]
R53  220  [Resistor 0805]
R54  220  [Resistor 0805]
R55  220  [Resistor 0805]
R56  220  [Resistor 0805]
R57  220  [Resistor 0805]
R58  220  [Resistor 0805]
R59  220  [Resistor 0805]
R60  220  [Resistor 0805]
R61  220  [Resistor 0805]
R62  220  [Resistor 0805]
R63  220  [Resistor 0805]
R64  220  [Resistor 0805]
R65  220  [Resistor 0805]
R66  220  [Resistor 0805]
R67  220  [Resistor 0805]
R68  220  [Resistor 0805]
R69  220  [Resistor 0805]
R70  220  [Resistor 0805]
R71  220  [Resistor 0805]
R72  220  [Resistor 0805]
R73  220  [Resistor 0805]
R74  220  [Resistor 0805]
R75  220  [Resistor 0805]
R76  220  [Resistor 0805]
R77  220  [Resistor 0805]
R78  220  [Resistor 0805]
R79  220  [Resistor 0805]
R80  220  [Resistor 0805]
R81  220  [Resistor 0805]
R82  220  [Resistor 0805]
R83  220  [Resistor 0805]
R84  220  [Resistor 0805]
T1  C1815  [SOT23-BCE]
T2  C1815  [SOT23-BCE]
T3  C1815  [SOT23-BCE]
T4  C1815  [SOT23-BCE]
T5  C1815  [SOT23-BCE]
T6  C1815  [SOT23-BCE]
T7  C1815  [SOT23-BCE]
T8  C1815  [SOT23-BCE]
T9  C1815  [SOT23-BCE]
T10  C1815  [SOT23-BCE]
T11  C1815  [SOT23-BCE]
T12  C1815  [SOT23-BCE]
T13  C1815  [SOT23-BCE]
T14  C1815  [SOT23-BCE]
T15  C1815  [SOT23-BCE]
T16  C1815  [SOT23-BCE]
T17  C1815  [SOT23-BCE]
T18  C1815  [SOT23-BCE]
T19  C1815  [SOT23-BCE]
T20  C1815  [SOT23-BCE]
T21  C1815  [SOT23-BCE]
T22  C1815  [SOT23-BCE]
T23  C1815  [SOT23-BCE]
T24  C1815  [SOT23-BCE]
T25  C1815  [SOT23-BCE]
T26  C1815  [SOT23-BCE]
T27  C1815  [SOT23-BCE]
T28  C1815  [SOT23-BCE]
T29  C1815  [SOT23-BCE]
T30  C1815  [SOT23-BCE]
T31  C1815  [SOT23-BCE]
T32  C1815  [SOT23-BCE]
T33  C1815  [SOT23-BCE]
T34  C1815  [SOT23-BCE]
T35  C1815  [SOT23-BCE]
T36  C1815  [SOT23-BCE]
T37  C1815  [SOT23-BCE]
T38  C1815  [SOT23-BCE]
T39  C1815  [SOT23-BCE]
T40  C1815  [SOT23-BCE]
T41  C1815  [SOT23-BCE]
T42  C1815  [SOT23-BCE]
U0  74HC540D -CONTROL LED  [hc540.SOIC-20_L12.8-W7.5-P1.27-LS10.3-]
U1  74HC540-DATA  [hc540.SOIC-20_L12.8-W7.5-P1.27-LS10.3-]
U2  74HC540-DATA-1  [hc540.SOIC-20_L12.8-W7.5-P1.27-LS10.3-]
U3  74HC540-DATA-2  [hc540.SOIC-20_L12.8-W7.5-P1.27-LS10.3-]

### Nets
+5: C1.2(-) C2.2(-) C3.2(-) C4.2(-) JP?.6 JP?.7 JP?.8 JP?.9 JP?.10 R1.2 R2.2 R5.2 R6.2 R9.2 R10.2 R15.2 R16.2 R18.2 R22.2 R24.2 R25.2 R27.2 R28.2 R35.2 R36.2 R37.2 R38.2 R39.2 R44.2 R45.2 R46.2 R47.2 R48.2 R53.2 R54.2 R55.2 R58.2 R59.2 R62.2 R63.2 R64.2 R67.2 R68.2 R71.2 R72.2 R73.2 R74.2 R75.2 R80.2 R81.2 R82.2 T1.2(C) T2.2(C) T3.2(C) T4.2(C) T5.2(C) T6.2(C) T7.2(C) T8.2(C) T9.2(C) T10.2(C) T11.2(C) T12.2(C) T13.2(C) T14.2(C) T15.2(C) T16.2(C) T17.2(C) T18.2(C) T19.2(C) T20.2(C) T21.2(C) T22.2(C) T23.2(C) T24.2(C) T25.2(C) T26.2(C) T27.2(C) T28.2(C) T29.2(C) T30.2(C) T31.2(C) T32.2(C) T33.2(C) T34.2(C) T35.2(C) T36.2(C) T37.2(C) T38.2(C) T39.2(C) T40.2(C) T41.2(C) T42.2(C)
GND: T1.3(E) T2.3(E) T3.3(E) T4.3(E) T5.3(E) T6.3(E) T7.3(E) T8.3(E) T9.3(E) T10.3(E) T11.3(E) T12.3(E) T13.3(E) T14.3(E) T15.3(E) T16.3(E) T17.3(E) T18.3(E) T19.3(E) T20.3(E) T21.3(E) T22.3(E) T23.3(E) T24.3(E) T25.3(E) T26.3(E) T27.3(E) T28.3(E) T29.3(E) T30.3(E) T31.3(E) T32.3(E) T33.3(E) T34.3(E) T35.3(E) T36.3(E) T37.3(E) T38.3(E) T39.3(E) T40.3(E) T41.3(E) T42.3(E) U0.1(OE1#) U0.10(GND) U0.19(OE2#) U1.1(OE1#) U1.10(GND) U1.19(OE2#) U2.1(OE1#) U2.10(GND) U2.19(OE2#) U3.1(OE1#) U3.10(GND) U3.19(OE2#)
A: R15.1
A0: JP1.1 U1.2(A0)
A1: JP1.2 R16.1 U1.3(A1)
A2: JP1.3 R18.1 U1.4(A2)
A3: JP1.4 U1.5(A3)
A4: JP1.5 U1.6(A4)
A5: JP1.6 U1.7(A5)
A6: JP1.7 U1.8(A6)
A7: JP1.8 U1.9(A7)
A8: JP1.9 U2.2(A0)
A9: JP1.10 U2.3(A1)
A10: JP1.11 U2.4(A2)
A11: JP1.12 U2.5(A3)
A12: JP1.13 U2.6(A4)
A13: JP1.14 U2.7(A5)
A14: JP1.15 U2.8(A6)
A15: JP1.16 U2.9(A7)
A16: JP1.17 U3.2(A0)
A17: JP1.18 U3.3(A1)
A18: JP1.19 U3.4(A2)
A19: JP1.20 U3.5(A3)
A20: JP1.21 U3.6(A4)
A21: JP1.22 U3.7(A5)
A22: JP1.23 U3.8(A6)
A23: JP1.24 U3.9(A7)
B: R22.1
B1: R24.1
B2: R25.1
C: R35.1
C1: JP1.40 R36.1 U0.2(A0)
C2: JP1.39 R37.1 U0.3(A1)
C3: JP1.38 U0.4(A2)
C4: JP1.37 U0.5(A3)
C5: JP1.36 U0.6(A4)
C6: JP1.35 U0.7(A5)
D: R44.1
D1: R45.1
D2: R46.1
E: R53.1
E1: R54.1
E2: R55.1
F: R62.1
F1: R63.1
F2: R64.1
G: R71.1
G1: R72.1
G2: R73.1
H: R80.1
H1: R81.1
H2: R82.1
L1: R3.2 R7.2 R12.2 U0.18(Y0#)
L2: R4.2 R8.2 R13.2 U0.17(Y1#)
L3: R33.2 R42.2 R51.2 U0.16(Y2#)
L4: R34.2 R43.2 R52.2 U0.15(Y3#)
L5: R60.2 R69.2 R78.2 U0.14(Y4#)
L6: R61.2 R70.2 R79.2 U0.13(Y5#)
LED1: R2.1
LED1.1: R6.1
LED1.2: R10.1
LED2: R1.1
LED2.1: R5.1
LED2.2: R9.1
LED3: R27.1
LED3.1: R38.1
LED3.2: R47.1
LED4: R28.1
LED4.1: R39.1
LED4.2: R48.1
LED5: R58.1 R67.1  [also labelled LED5.1]
LED5.2: R74.1
LED6: R59.1
LED6.1: R68.1
LED6.2: R75.1
Y0: R11.2 U1.18(Y0#)
Y1: R14.2 U1.17(Y1#)
Y2: R17.2 U1.16(Y2#)
Y3: R20.2 U1.15(Y3#)
Y4: R23.2 U1.14(Y4#)
Y5: R26.2 U1.13(Y5#)
Y6: R29.2 U1.12(Y6#)
Y7: R30.2 U1.11(Y7#)
Y8: R19.2 U2.18(Y0#)
Y9: R31.2 U2.17(Y1#)
Y10: R40.2 U2.16(Y2#)
Y11: R49.2 U2.15(Y3#)
Y12: R56.2 U2.14(Y4#)
Y13: R65.2 U2.13(Y5#)
Y14: R76.2 U2.12(Y6#)
Y15: R83.2 U2.11(Y7#)
Y16: R21.2 U3.18(Y0#)
Y17: R32.2 U3.17(Y1#)
Y18: R41.2 U3.16(Y2#)
Y19: R50.2 U3.15(Y3#)
Y20: R57.2 U3.14(Y4#)
Y21: R66.2 U3.13(Y5#)
Y22: R77.2 U3.12(Y6#)
Y23: R84.2 U3.11(Y7#)
NetC1_1: C1.1(+) U0.20(VCC)
NetC2_1: C2.1(+) U1.20(VCC)
NetC3_1: C3.1(+) U2.20(VCC)
NetC4_1: C4.1(+) U3.20(VCC)
NetR3_1: R3.1 T1.1(B)
NetR4_1: R4.1 T2.1(B)
NetR7_1: R7.1 T3.1(B)
NetR8_1: R8.1 T4.1(B)
NetR11_1: R11.1 T5.1(B)
NetR12_1: R12.1 T6.1(B)
NetR13_1: R13.1 T7.1(B)
NetR14_1: R14.1 T8.1(B)
NetR17_1: R17.1 T11.1(B)
NetR19_1: R19.1 T9.1(B)
NetR20_1: R20.1 T14.1(B)
NetR21_1: R21.1 T10.1(B)
NetR23_1: R23.1 T17.1(B)
NetR26_1: R26.1 T20.1(B)
NetR29_1: R29.1 T23.1(B)
NetR30_1: R30.1 T24.1(B)
NetR31_1: R31.1 T12.1(B)
NetR32_1: R32.1 T13.1(B)
NetR33_1: R33.1 T15.1(B)
NetR34_1: R34.1 T16.1(B)
NetR40_1: R40.1 T18.1(B)
NetR41_1: R41.1 T19.1(B)
NetR42_1: R42.1 T21.1(B)
NetR43_1: R43.1 T22.1(B)
NetR49_1: R49.1 T25.1(B)
NetR50_1: R50.1 T26.1(B)
NetR51_1: R51.1 T27.1(B)
NetR52_1: R52.1 T28.1(B)
NetR56_1: R56.1 T29.1(B)
NetR57_1: R57.1 T30.1(B)
NetR60_1: R60.1 T31.1(B)
NetR61_1: R61.1 T32.1(B)
NetR65_1: R65.1 T33.1(B)
NetR66_1: R66.1 T34.1(B)
NetR69_1: R69.1 T35.1(B)
NetR70_1: R70.1 T36.1(B)
NetR76_1: R76.1 T37.1(B)
NetR77_1: R77.1 T38.1(B)
NetR78_1: R78.1 T39.1(B)
NetR79_1: R79.1 T40.1(B)
NetR83_1: R83.1 T41.1(B)
NetR84_1: R84.1 T42.1(B)

Not connected (* = marked no-connect by the designer): JP1 25* 26* 27* 28* 29* 30* 31* 32* 33* 34*; JP? 1* 2* 3* 4* 5*; U0 8(A6)* 9(A7)* 11(Y7#)* 12(Y6#)*

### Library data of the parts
C1-C4 = CAP SMD: Capacitor Polarised; Manufacturer_Name: AVX; Manufacturer_Part_Number: TAJC227K006RNJV
JP1 = JP 2x20 2.54 Duc Thang: Cắm; Ten_Linh_Kien: Jump Đôi Đực 2.54MM 2x40P Thẳng 11MM; Don_Vi: Con; Ma_Hang: MH002686
JP? = JP 1x10 2.54 Duc Thang: Cắm; Ten_Linh_Kien: Jump Đơn Đực 2.54MM 1x40P Thẳng 11MM; Don_Vi: Con; Ma_Hang: MH000903
R1-R84 = Resistor
T1-T42 = 2SC1815: Bipolar Transistors - BJT NPN Epitaxial Sil
U0-U3 = 74HC540D,653: Manufacturer: Nexperia(安世); Add into BOM: yes

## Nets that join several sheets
A: 7seg_display_SCHE (18 pins), ic_display_SCHE (R15.1)
A1: 7seg_display_SCHE (18 pins), ic_display_SCHE (JP1.2 R16.1 U1.3)
A2: 7seg_display_SCHE (18 pins), ic_display_SCHE (JP1.3 R18.1 U1.4)
B: 7seg_display_SCHE (24 pins), ic_display_SCHE (R22.1)
B1: 7seg_display_SCHE (24 pins), ic_display_SCHE (R24.1)
B2: 7seg_display_SCHE (24 pins), ic_display_SCHE (R25.1)
C: 7seg_display_SCHE (30 pins), ic_display_SCHE (R35.1)
C1: 7seg_display_SCHE (30 pins), ic_display_SCHE (JP1.40 R36.1 U0.2)
C2: 7seg_display_SCHE (30 pins), ic_display_SCHE (JP1.39 R37.1 U0.3)
D: 7seg_display_SCHE (18 pins), ic_display_SCHE (R44.1)
D1: 7seg_display_SCHE (18 pins), ic_display_SCHE (R45.1)
D2: 7seg_display_SCHE (18 pins), ic_display_SCHE (R46.1)
E: 7seg_display_SCHE (30 pins), ic_display_SCHE (R53.1)
E1: 7seg_display_SCHE (30 pins), ic_display_SCHE (R54.1)
E2: 7seg_display_SCHE (30 pins), ic_display_SCHE (R55.1)
F: 7seg_display_SCHE (30 pins), ic_display_SCHE (R62.1)
F1: 7seg_display_SCHE (30 pins), ic_display_SCHE (R63.1)
F2: 7seg_display_SCHE (30 pins), ic_display_SCHE (R64.1)
G: 7seg_display_SCHE (18 pins), ic_display_SCHE (R71.1)
G1: 7seg_display_SCHE (18 pins), ic_display_SCHE (R72.1)
G2: 7seg_display_SCHE (18 pins), ic_display_SCHE (R73.1)
H: 7seg_display_SCHE (6 pins), ic_display_SCHE (R80.1)
H1: 7seg_display_SCHE (6 pins), ic_display_SCHE (R81.1)
H2: 7seg_display_SCHE (6 pins), ic_display_SCHE (R82.1)
LED1: 7seg_display_SCHE (29 pins), ic_display_SCHE (R2.1)
LED1.1: 7seg_display_SCHE (34 pins), ic_display_SCHE (R6.1)
LED1.2: 7seg_display_SCHE (24 pins), ic_display_SCHE (R10.1)
LED2: 7seg_display_SCHE (29 pins), ic_display_SCHE (R1.1)
LED2.1: 7seg_display_SCHE (29 pins), ic_display_SCHE (R5.1)
LED2.2: 7seg_display_SCHE (29 pins), ic_display_SCHE (R9.1)
LED3: 7seg_display_SCHE (32 pins), ic_display_SCHE (R27.1)
LED3.1: 7seg_display_SCHE (29 pins), ic_display_SCHE (R38.1)
LED3.2: 7seg_display_SCHE (26 pins), ic_display_SCHE (R47.1)
LED4: 7seg_display_SCHE (29 pins), ic_display_SCHE (R28.1)
LED4.1: 7seg_display_SCHE (29 pins), ic_display_SCHE (R39.1)
LED4.2: 7seg_display_SCHE (29 pins), ic_display_SCHE (R48.1)
LED5: 7seg_display_SCHE (58 pins), ic_display_SCHE (R58.1 R67.1)
LED5.2: 7seg_display_SCHE (29 pins), ic_display_SCHE (R74.1)
LED6: 7seg_display_SCHE (29 pins), ic_display_SCHE (R59.1)
LED6.1: 7seg_display_SCHE (29 pins), ic_display_SCHE (R68.1)
LED6.2: 7seg_display_SCHE (29 pins), ic_display_SCHE (R75.1)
